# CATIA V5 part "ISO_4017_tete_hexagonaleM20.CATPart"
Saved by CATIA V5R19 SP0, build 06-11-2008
Part number: ISO_4017_M_20_80
Nomenclature: Vis H M 20 80
Source: bought
Description: ISO 4017
Publications: "Axe", "Appui"
Material "Acier": density 7860 kg/m3, Young's modulus 2e+11 Pa, Poisson ratio 0.266, thermal expansion 1.17e-05 1/K
Bounding box of the stored display mesh (mm): x -80 to 12.715, y -15 to 15, z -17.321 to 17.321
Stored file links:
  G:\EU_thinkMotion\CFAO_2010\MMS_groupe2\MMS_groupe2\OK\melguidj\cfao_elguidj_2AMMSgrB\Modèle 3D\ISO_4017_tete_hexagonaleM20.CATPart
  C:\Users\Martin\Documents\IFMA\Cfao\Projet S3\Bibliothèque Catia\ISO_4017_tete hexagonale.txt
  C:\Users\Martin\Documents\IFMA\Cfao\Projet S3\Bibliothèque Catia\MetricThickPitch.txt
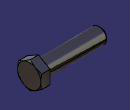
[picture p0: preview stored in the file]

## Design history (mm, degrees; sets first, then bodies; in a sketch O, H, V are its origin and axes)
Parameters
  Designation = "Vis H M 20 80" {design table}
  d_diametre_nominal = 20 mm {design table}
  l_longueur = 80 mm {design table}
  hauteur_tete_max = 12.715 mm {design table}
  r_min = 0.8 mm {design table}
  s_cote_sur_plat = 30 mm {design table}
  diametre_appui_tete_min = 28.19 mm {design table}
  c_max = 0.8 mm {design table}
  P_pas = 2.5 mm {design table}
  C2_diametre_lamage = 64 mm {design table}
  d1_fin_trou_lisse = 20 mm
  d1_moyen_trou_lisse = 20 mm
  d1_large_trou_lisse = 20 mm
  PartNumber = "ISO_4017_M_20_80" {design table}
Body1 "ISO_4017" (main body)
  Sketch1 on yz-plane, origin (0, 0, 0), H (0, 1, 0), V (0, 0, 1)
    circle A1 centre (0, 0) radius 14.095
    radius A1 = 14.095 {= diametre_appui_tete_min /2}
  Pad1: profile Sketch1, direction (1, 0, 0), length 0.8 {= c_max}
  Sketch2 on face of Pad1, origin (0.8, 0, 0), H (0, 1, 0), V (0, 0, 1)
    point P1 (15, -8.6603)
    point P2 (15, 8.6603)
    point P3 (0, 17.3205)
    point P4 (-15, 8.6603)
    point P5 (-15, -8.6603)
    point P6 (0, -17.3205)
    point P7 (15, 0)
    line L1 (15, -8.6603) -> (15, 8.6603)
    line L2 (15, 8.6603) -> (0, 17.3205)
    line L3 (0, 17.3205) -> (-15, 8.6603)
    line L4 (-15, 8.6603) -> (-15, -8.6603)
    line L5 (-15, -8.6603) -> (0, -17.3205)
    line L6 (0, -17.3205) -> (15, -8.6603)
    construction line L7 (0, 0) -> (15, 0)
    construction circle A1 centre (0, 0) radius 17.3205
    construction arc A2 centre (-15, -8.6603) radius 17.3205 from (-15, 8.6603) to (0, -17.3205) cw
    construction arc A3 centre (15, 8.6603) radius 17.3205 from (0, 17.3205) to (15, -8.6603) ccw
    point P8 (-15, -8.6603)
    point P9 (15, 8.6603)
    distance L1 L4 = 30 {= s_cote_sur_plat}
    horizontal: L7 H
    coincidence: A1 P1, A1 P2, A1 P3, A1 P4, A1 P5, A1 P6, A2 P4, A2 P6, A2 O, P8 P5, A3 P3, A3 P1, A3 O, P9 P2
    midpoint: P7 L1
  Pad2: profile Sketch2, direction (1, 0, 0), length 11.915 {= hauteur_tete_max -c_max}
  Sketch3 on zx-plane, origin (0, 0, 0), H (-1, 0, 0), V (0, 0, 1)
    point P1 (-12.715, 14.9925)
    axis line L1 (-94.6904, 0) -> (76.7146, 0)
    reference intersected line E1 through (1000000, 0) direction (-1, 0) from xy-plane
    line L2 (-11.3709, 17.3205) -> (-12.715, 14.9925)
    line L3 (-11.3709, 17.3205) -> (-12.715, 17.3205)
    line L4 (-12.715, 17.3205) -> (-12.715, 14.9925)
    reference projected line E2 (-0.8, 17.3205) -> (-18.28, 17.3205) from edge [face of Pad2 | face of Pad2]
    distance P1 H = 14.9925 {= s_cote_sur_plat /2.001}
    distance P1 V = 12.715 {= hauteur_tete_max}
    angle L4 L2 = 30
    horizontal: L1 H, L3 H
    coincidence: L1 E1, L3 E2
    vertical: L4 V
  Groove1: profile Sketch3, axis Sketch3.L1, angle 360
  Sketch4 on face of Pad1, origin (0, 0, 0), H (0, -1, 0), V (0, 0, 1)
    circle A1 centre (0, 0) radius 10
    radius A1 = 10 {= d_diametre_nominal /2.0}
  Pad3: profile Sketch4, direction (-1, 0, 0), length 80 {= l_longueur}
  Thread1: "M20", diameter 20 {= d_diametre_nominal}, depth 79.2 {= l_longueur -Fillet1.Radius}, pitch 2.5 {= P_pas}
  Fillet1: radius 0.8 {= r_min}, on edge [face of Pad3 | face of Pad1]
  Chamfer1: length 2.5 {= P_pas}, angle 45, on edge [face of Pad3 | face of Pad3]
Relations
  design table, configuration 133, drives Designation, d_diametre_nominal, l_longueur, diametre_appui_tete_min, c_max, P_pas, r_min, s_cote_sur_plat, hauteur_tete_max, C2_diametre_lamage, PartNumber, Thread1.ThreadDescription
